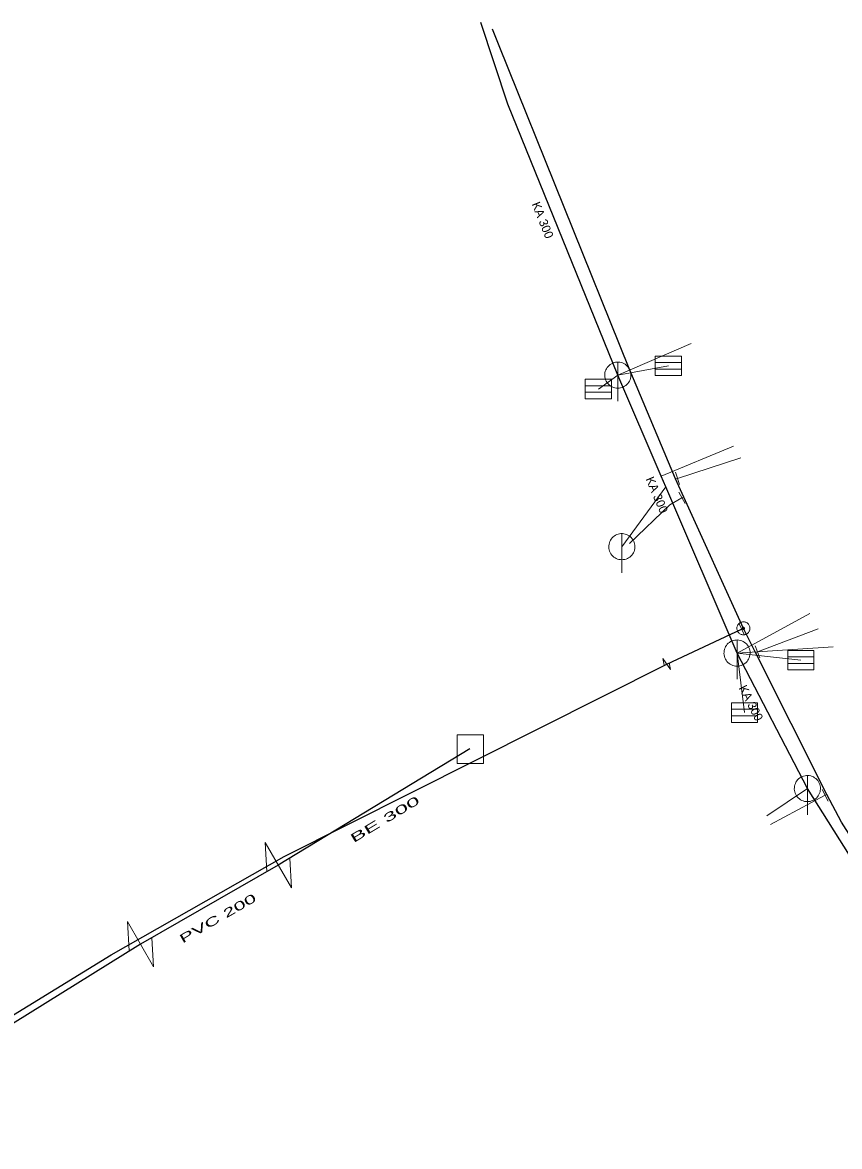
# Model space of a CAD drawing. Extents: x -688296 to -687852, y -973332 to -972816.
# Drawn here: x -687998.3 to -687935.8, y -973111.5 to -973025.5 of the extents above; entities that cross this region are included whole.
import ezdxf
from ezdxf.enums import TextEntityAlignment as Align

# ---------------------------------------------------------------- set-up
doc = ezdxf.new("R2010")
doc.units = 0
doc.header["$LTSCALE"] = 0.27
for name, color, linetype, lineweight in [('1', 7, 'Continuous', 25), ('11', 7, 'Continuous', 13), ('13', 7, 'Continuous', 13), ('14', 7, 'Continuous', 13), ('17', 7, 'Continuous', 25), ('22', 7, 'Continuous', 13), ('31', 7, 'Continuous', 13), ('34', 7, 'Continuous', 13), ('47', 7, 'Continuous', 13)]:
    doc.layers.add(name, color=color, linetype=linetype, lineweight=lineweight)

msp = doc.modelspace()

# ---------------------------------------------------------------- linework, layer by layer
at = {"layer": '11'}
for p, q in [((-687947.14, -973050.03), (-687952.739, -973052.449)), ((-687948.859, -973051.75), (-687952.739, -973052.449)), ((-687954.219, -973053.52), (-687952.739, -973052.449)), ((-687943.899, -973057.879), (-687949.42, -973060.19)), ((-687952.43, -973065.579), (-687949.07, -973061)), ((-687938.039, -973070.69), (-687943.62, -973073.719)), ((-687936.26, -973073.25), (-687943.62, -973073.719)), ((-687943.039, -973078.28), (-687943.62, -973073.719)), ((-687938.73, -973074.27), (-687943.62, -973073.719)), ((-687941.34, -973086.17), (-687938.239, -973084.09))]:
    msp.add_line(p, q, dxfattribs=at)
at = {"layer": '13'}
for p, q in [((-687948.176, -973060.353), (-687943.34, -973058.789)), ((-687942.059, -973073.627), (-687937.41, -973071.87)), ((-687936.871, -973084.6), (-687941.07, -973086.85))]:
    msp.add_line(p, q, dxfattribs=at)
msp.add_lwpolyline([(-687947.829, -973061.853), (-687948.77, -973062.39), (-687951.85, -973065.34)], dxfattribs=at)
at = {"layer": '14'}
for p, q in [((-687948.32, -973060.399), (-687948.176, -973060.353)), ((-687947.699, -973061.78), (-687947.829, -973061.853)), ((-687943.129, -973071.829), (-687943.265, -973071.892)), ((-687942.199, -973073.68), (-687942.059, -973073.627)), ((-687936.739, -973084.53), (-687936.871, -973084.6))]:
    msp.add_line(p, q, dxfattribs=at)
at = {"layer": '14', "lineweight": 25}
for p, q in [((-687938.239, -973084.09), (-687943.62, -973073.719)), ((-687964.059, -973081.057), (-687978.709, -973089.949)), ((-687978.709, -973089.949), (-687989.249, -973096)), ((-687989.249, -973096), (-688026.18, -973118.949))]:
    msp.add_line(p, q, dxfattribs=at)
for points in [[(-687952.739, -973052.449), (-687961.14, -973031.719), (-687963.23, -973025.469)], [(-687943.62, -973073.719), (-687949.07, -973061), (-687949.42, -973060.19), (-687952.739, -973052.449)], [(-687924.829, -973105.26), (-687930.94, -973095.67), (-687938.239, -973084.09)]]:
    msp.add_lwpolyline(points, dxfattribs=at)
at = {"layer": '17'}
msp.add_line((-687949, -973074.559), (-687943.265, -973071.892), dxfattribs=at)
for points in [[(-687943.129, -973071.829), (-687947.699, -973061.78), (-687948.32, -973060.399), (-687951.879, -973051.94), (-687961.809, -973027.26), (-687962.319, -973025.989)], [(-687923.279, -973105.989), (-687929, -973097.05), (-687935.64, -973086.66), (-687936.739, -973084.53), (-687942.199, -973073.68), (-687943.129, -973071.829)], [(-688063.439, -973127.129), (-688055.41, -973136.87), (-688027.175, -973118.732), (-687991.487, -973096.813), (-687978.252, -973089.283), (-687949, -973074.559)]]:
    msp.add_lwpolyline(points, dxfattribs=at)
at = {"layer": '22'}
for p, q in [((-687952.739, -973054.449), (-687952.738, -973051.449)), ((-687949.871, -973051.493), (-687947.871, -973051.493)), ((-687949.871, -973051.993), (-687947.871, -973051.993)), ((-687955.23, -973053.263), (-687953.23, -973053.263)), ((-687955.23, -973053.763), (-687953.23, -973053.763)), ((-687952.43, -973067.579), (-687952.429, -973064.579)), ((-687943.62, -973075.719), (-687943.619, -973072.719)), ((-687939.741, -973074.013), (-687937.741, -973074.013)), ((-687939.741, -973074.513), (-687937.741, -973074.513)), ((-687944.05, -973078.023), (-687942.05, -973078.023)), ((-687944.05, -973078.523), (-687942.05, -973078.523)), ((-687938.239, -973086.09), (-687938.238, -973083.09))]:
    msp.add_line(p, q, dxfattribs=at)
for points in [[(-687949.871, -973050.993), (-687947.871, -973050.993), (-687947.871, -973052.493), (-687949.871, -973052.493)], [(-687951.739, -973052.449), (-687951.744, -973052.34), (-687951.762, -973052.232), (-687951.792, -973052.126), (-687951.832, -973052.025), (-687951.884, -973051.928), (-687951.946, -973051.838), (-687952.018, -973051.755), (-687952.098, -973051.681), (-687952.186, -973051.615), (-687952.28, -973051.56), (-687952.38, -973051.515), (-687952.485, -973051.482), (-687952.592, -973051.46), (-687952.701, -973051.45), (-687952.811, -973051.452), (-687952.919, -973051.466), (-687953.026, -973051.491), (-687953.129, -973051.528), (-687953.227, -973051.577), (-687953.319, -973051.635), (-687953.405, -973051.704), (-687953.482, -973051.781), (-687953.551, -973051.867), (-687953.61, -973051.959), (-687953.658, -973052.057), (-687953.695, -973052.16), (-687953.721, -973052.267), (-687953.735, -973052.375), (-687953.738, -973052.485), (-687953.728, -973052.594), (-687953.707, -973052.701), (-687953.673, -973052.805), (-687953.629, -973052.905), (-687953.574, -973053), (-687953.508, -973053.088), (-687953.434, -973053.168), (-687953.351, -973053.24), (-687953.261, -973053.302), (-687953.165, -973053.354), (-687953.063, -973053.395), (-687952.958, -973053.425), (-687952.85, -973053.443), (-687952.74, -973053.449), (-687952.631, -973053.443), (-687952.523, -973053.425), (-687952.418, -973053.396), (-687952.316, -973053.355), (-687952.219, -973053.303), (-687952.129, -973053.241), (-687952.046, -973053.17), (-687951.971, -973053.09), (-687951.906, -973053.002), (-687951.85, -973052.908), (-687951.806, -973052.808), (-687951.772, -973052.704), (-687951.75, -973052.596), (-687951.74, -973052.487)], [(-687955.23, -973052.763), (-687953.23, -973052.763), (-687953.23, -973054.263), (-687955.23, -973054.263)], [(-687951.43, -973065.579), (-687951.435, -973065.47), (-687951.453, -973065.362), (-687951.483, -973065.256), (-687951.523, -973065.155), (-687951.575, -973065.058), (-687951.637, -973064.968), (-687951.709, -973064.885), (-687951.789, -973064.811), (-687951.877, -973064.745), (-687951.971, -973064.69), (-687952.071, -973064.645), (-687952.176, -973064.612), (-687952.283, -973064.59), (-687952.392, -973064.58), (-687952.502, -973064.582), (-687952.61, -973064.596), (-687952.717, -973064.621), (-687952.82, -973064.658), (-687952.918, -973064.707), (-687953.01, -973064.765), (-687953.096, -973064.834), (-687953.173, -973064.911), (-687953.242, -973064.997), (-687953.301, -973065.089), (-687953.349, -973065.187), (-687953.386, -973065.29), (-687953.412, -973065.397), (-687953.426, -973065.505), (-687953.429, -973065.615), (-687953.419, -973065.724), (-687953.398, -973065.831), (-687953.364, -973065.935), (-687953.32, -973066.035), (-687953.265, -973066.13), (-687953.199, -973066.218), (-687953.125, -973066.298), (-687953.042, -973066.37), (-687952.952, -973066.432), (-687952.856, -973066.484), (-687952.754, -973066.525), (-687952.649, -973066.555), (-687952.541, -973066.573), (-687952.431, -973066.579), (-687952.322, -973066.573), (-687952.214, -973066.555), (-687952.109, -973066.526), (-687952.007, -973066.485), (-687951.91, -973066.433), (-687951.82, -973066.371), (-687951.737, -973066.3), (-687951.662, -973066.22), (-687951.597, -973066.132), (-687951.541, -973066.038), (-687951.497, -973065.938), (-687951.463, -973065.834), (-687951.441, -973065.726), (-687951.431, -973065.617)], [(-687942.62, -973073.719), (-687942.625, -973073.61), (-687942.643, -973073.502), (-687942.673, -973073.396), (-687942.713, -973073.295), (-687942.765, -973073.198), (-687942.827, -973073.108), (-687942.899, -973073.025), (-687942.979, -973072.951), (-687943.067, -973072.885), (-687943.161, -973072.83), (-687943.261, -973072.785), (-687943.366, -973072.752), (-687943.473, -973072.73), (-687943.582, -973072.72), (-687943.692, -973072.722), (-687943.8, -973072.736), (-687943.907, -973072.761), (-687944.01, -973072.798), (-687944.108, -973072.847), (-687944.2, -973072.905), (-687944.286, -973072.974), (-687944.363, -973073.051), (-687944.432, -973073.137), (-687944.491, -973073.229), (-687944.539, -973073.327), (-687944.576, -973073.43), (-687944.602, -973073.537), (-687944.616, -973073.645), (-687944.619, -973073.755), (-687944.609, -973073.864), (-687944.588, -973073.971), (-687944.554, -973074.075), (-687944.51, -973074.175), (-687944.455, -973074.27), (-687944.389, -973074.358), (-687944.315, -973074.438), (-687944.232, -973074.51), (-687944.142, -973074.572), (-687944.046, -973074.624), (-687943.944, -973074.665), (-687943.839, -973074.695), (-687943.731, -973074.713), (-687943.621, -973074.719), (-687943.512, -973074.713), (-687943.404, -973074.695), (-687943.299, -973074.666), (-687943.197, -973074.625), (-687943.1, -973074.573), (-687943.01, -973074.511), (-687942.927, -973074.44), (-687942.852, -973074.36), (-687942.787, -973074.272), (-687942.731, -973074.178), (-687942.687, -973074.078), (-687942.653, -973073.974), (-687942.631, -973073.866), (-687942.621, -973073.757)], [(-687939.741, -973073.513), (-687937.741, -973073.513), (-687937.741, -973075.013), (-687939.741, -973075.013)], [(-687944.05, -973077.523), (-687942.05, -973077.523), (-687942.05, -973079.023), (-687944.05, -973079.023)], [(-687965.039, -973079.967), (-687963.006, -973079.967), (-687963.006, -973082.16), (-687965.039, -973082.16)], [(-687937.239, -973084.09), (-687937.244, -973083.981), (-687937.262, -973083.873), (-687937.292, -973083.767), (-687937.332, -973083.666), (-687937.384, -973083.569), (-687937.446, -973083.479), (-687937.518, -973083.396), (-687937.598, -973083.322), (-687937.686, -973083.256), (-687937.78, -973083.201), (-687937.88, -973083.156), (-687937.985, -973083.123), (-687938.092, -973083.101), (-687938.201, -973083.091), (-687938.311, -973083.093), (-687938.419, -973083.107), (-687938.526, -973083.132), (-687938.629, -973083.169), (-687938.727, -973083.218), (-687938.819, -973083.276), (-687938.905, -973083.345), (-687938.982, -973083.422), (-687939.051, -973083.508), (-687939.11, -973083.6), (-687939.158, -973083.698), (-687939.195, -973083.801), (-687939.221, -973083.908), (-687939.235, -973084.016), (-687939.238, -973084.126), (-687939.228, -973084.235), (-687939.207, -973084.342), (-687939.173, -973084.446), (-687939.129, -973084.546), (-687939.074, -973084.641), (-687939.008, -973084.729), (-687938.934, -973084.809), (-687938.851, -973084.881), (-687938.761, -973084.943), (-687938.665, -973084.995), (-687938.563, -973085.036), (-687938.458, -973085.066), (-687938.35, -973085.084), (-687938.24, -973085.09), (-687938.131, -973085.084), (-687938.023, -973085.066), (-687937.918, -973085.037), (-687937.816, -973084.996), (-687937.719, -973084.944), (-687937.629, -973084.882), (-687937.546, -973084.811), (-687937.471, -973084.731), (-687937.406, -973084.643), (-687937.35, -973084.549), (-687937.306, -973084.449), (-687937.272, -973084.345), (-687937.25, -973084.237), (-687937.24, -973084.128)]]:
    msp.add_lwpolyline(points, close=True, dxfattribs=at)
at = {"layer": '31'}
for points in [[(-687979.576, -973090.447), (-687979.704, -973088.214), (-687977.713, -973091.683), (-687977.841, -973089.451)], [(-687990.116, -973096.498), (-687990.244, -973094.265), (-687988.253, -973097.734), (-687988.381, -973095.502)]]:
    msp.add_lwpolyline(points, dxfattribs=at)
at = {"layer": '34'}
for p, q in [((-687948.33, -973059.877), (-687948.022, -973060.828)), ((-687948.077, -973061.418), (-687947.581, -973062.287)), ((-687943.476, -973071.438), (-687943.054, -973072.345)), ((-687942.236, -973073.159), (-687941.882, -973074.094)), ((-687937.107, -973084.159), (-687936.635, -973085.04))]:
    msp.add_line(p, q, dxfattribs=at)
at = {"layer": '47'}
msp.add_line((-687949.299, -973074.146), (-687949.182, -973074.643), dxfattribs=at)
for points in [[(-687942.904, -973072.275), (-687942.859, -973072.249), (-687942.816, -973072.219), (-687942.778, -973072.184), (-687942.742, -973072.146), (-687942.711, -973072.103), (-687942.684, -973072.057), (-687942.663, -973072.01), (-687942.647, -973071.96), (-687942.635, -973071.91), (-687942.629, -973071.857), (-687942.629, -973071.805), (-687942.635, -973071.753), (-687942.645, -973071.702), (-687942.661, -973071.652), (-687942.682, -973071.604), (-687942.708, -973071.559), (-687942.738, -973071.516), (-687942.774, -973071.477), (-687942.811, -973071.442), (-687942.854, -973071.411), (-687942.9, -973071.384), (-687942.947, -973071.363), (-687942.997, -973071.346), (-687943.048, -973071.335), (-687943.1, -973071.329), (-687943.152, -973071.329), (-687943.205, -973071.334), (-687943.255, -973071.345), (-687943.305, -973071.361), (-687943.353, -973071.382), (-687943.398, -973071.408), (-687943.441, -973071.438), (-687943.481, -973071.473), (-687943.515, -973071.511), (-687943.546, -973071.554), (-687943.573, -973071.599), (-687943.595, -973071.647), (-687943.611, -973071.696), (-687943.622, -973071.748), (-687943.628, -973071.8), (-687943.628, -973071.852), (-687943.623, -973071.904), (-687943.612, -973071.955), (-687943.596, -973072.005), (-687943.575, -973072.053), (-687943.549, -973072.098), (-687943.519, -973072.141), (-687943.485, -973072.18), (-687943.446, -973072.215), (-687943.403, -973072.246), (-687943.358, -973072.273), (-687943.311, -973072.294), (-687943.261, -973072.31), (-687943.21, -973072.322), (-687943.157, -973072.328), (-687943.105, -973072.328), (-687943.054, -973072.323), (-687943.002, -973072.312), (-687942.952, -973072.296)], [(-687943.092, -973071.902), (-687943.084, -973071.898), (-687943.077, -973071.892), (-687943.071, -973071.887), (-687943.065, -973071.881), (-687943.06, -973071.874), (-687943.056, -973071.866), (-687943.052, -973071.858), (-687943.049, -973071.85), (-687943.048, -973071.842), (-687943.047, -973071.833), (-687943.047, -973071.824), (-687943.048, -973071.816), (-687943.049, -973071.808), (-687943.051, -973071.8), (-687943.055, -973071.792), (-687943.059, -973071.784), (-687943.065, -973071.777), (-687943.07, -973071.771), (-687943.076, -973071.765), (-687943.083, -973071.76), (-687943.091, -973071.756), (-687943.099, -973071.752), (-687943.107, -973071.749), (-687943.116, -973071.747), (-687943.124, -973071.747), (-687943.133, -973071.747), (-687943.141, -973071.748), (-687943.149, -973071.749), (-687943.157, -973071.751), (-687943.165, -973071.755), (-687943.173, -973071.759), (-687943.18, -973071.765), (-687943.186, -973071.77), (-687943.192, -973071.776), (-687943.197, -973071.783), (-687943.201, -973071.79), (-687943.205, -973071.799), (-687943.208, -973071.807), (-687943.21, -973071.816), (-687943.21, -973071.824), (-687943.21, -973071.833), (-687943.209, -973071.841), (-687943.208, -973071.849), (-687943.206, -973071.857), (-687943.202, -973071.865), (-687943.198, -973071.873), (-687943.192, -973071.88), (-687943.187, -973071.886), (-687943.181, -973071.892), (-687943.174, -973071.897), (-687943.167, -973071.901), (-687943.158, -973071.905), (-687943.15, -973071.908), (-687943.142, -973071.909), (-687943.133, -973071.91), (-687943.124, -973071.91), (-687943.116, -973071.909), (-687943.108, -973071.908), (-687943.1, -973071.906)]]:
    msp.add_lwpolyline(points, close=True, dxfattribs=at)
msp.add_lwpolyline([(-687949.299, -973074.146), (-687948.7, -973074.971), (-687948.817, -973074.474)], dxfattribs=at)

# ---------------------------------------------------------------- texts
at = {"layer": '1'}
for rotation, p in [(292, (-687958.7966, -973040.7164)), (292, (-687958.7966, -973040.7164)), (292, (-687958.7966, -973040.7164)), (292, (-687958.7966, -973040.7164)), (292, (-687958.7966, -973040.7164)), (293, (-687950.053, -973061.7446)), (293, (-687950.053, -973061.7446)), (293, (-687950.053, -973061.7446)), (293, (-687950.053, -973061.7446)), (293, (-687950.053, -973061.7446)), (297, (-687942.8453, -973077.6905)), (297, (-687942.8453, -973077.6905)), (297, (-687942.8453, -973077.6905)), (297, (-687942.8453, -973077.6905)), (297, (-687942.8453, -973077.6905))]:
    msp.add_text('KA 300', height=0.6667, rotation=rotation, dxfattribs=at).set_placement(p, align=Align.CENTER)
for s, rotation, width, p in [('BE 300', 31, 2.05, (-687970.3857, -973086.7216)), ('BE 300', 31, 2.05, (-687970.3857, -973086.7216)), ('BE 300', 31, 2.05, (-687970.3857, -973086.7216)), ('BE 300', 31, 2.05, (-687970.3857, -973086.7216)), ('BE 300', 31, 2.05, (-687970.3857, -973086.7216)), ('PVC 200 ', 30, 1.85, (-687982.9757, -973094.1876)), ('PVC 200 ', 30, 1.85, (-687982.9757, -973094.1876)), ('PVC 200 ', 30, 1.85, (-687982.9757, -973094.1876)), ('PVC 200 ', 30, 1.85, (-687982.9757, -973094.1876)), ('PVC 200 ', 30, 1.85, (-687982.9757, -973094.1876))]:
    msp.add_text(s, height=0.6667, rotation=rotation, dxfattribs=dict(at, width=width)).set_placement(p, align=Align.CENTER)

doc.saveas('drawing.dxf')
